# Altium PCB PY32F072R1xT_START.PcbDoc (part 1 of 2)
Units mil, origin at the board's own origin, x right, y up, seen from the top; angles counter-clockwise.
Board outline 1771.65 x 3925.12 mil, 2 copper layers (Top Layer, Bottom Layer), stack 21 mil thick; 156 components, 167 nets, 616 pads, 288 vias.
Unrouted connection lines stored in the file: 5.
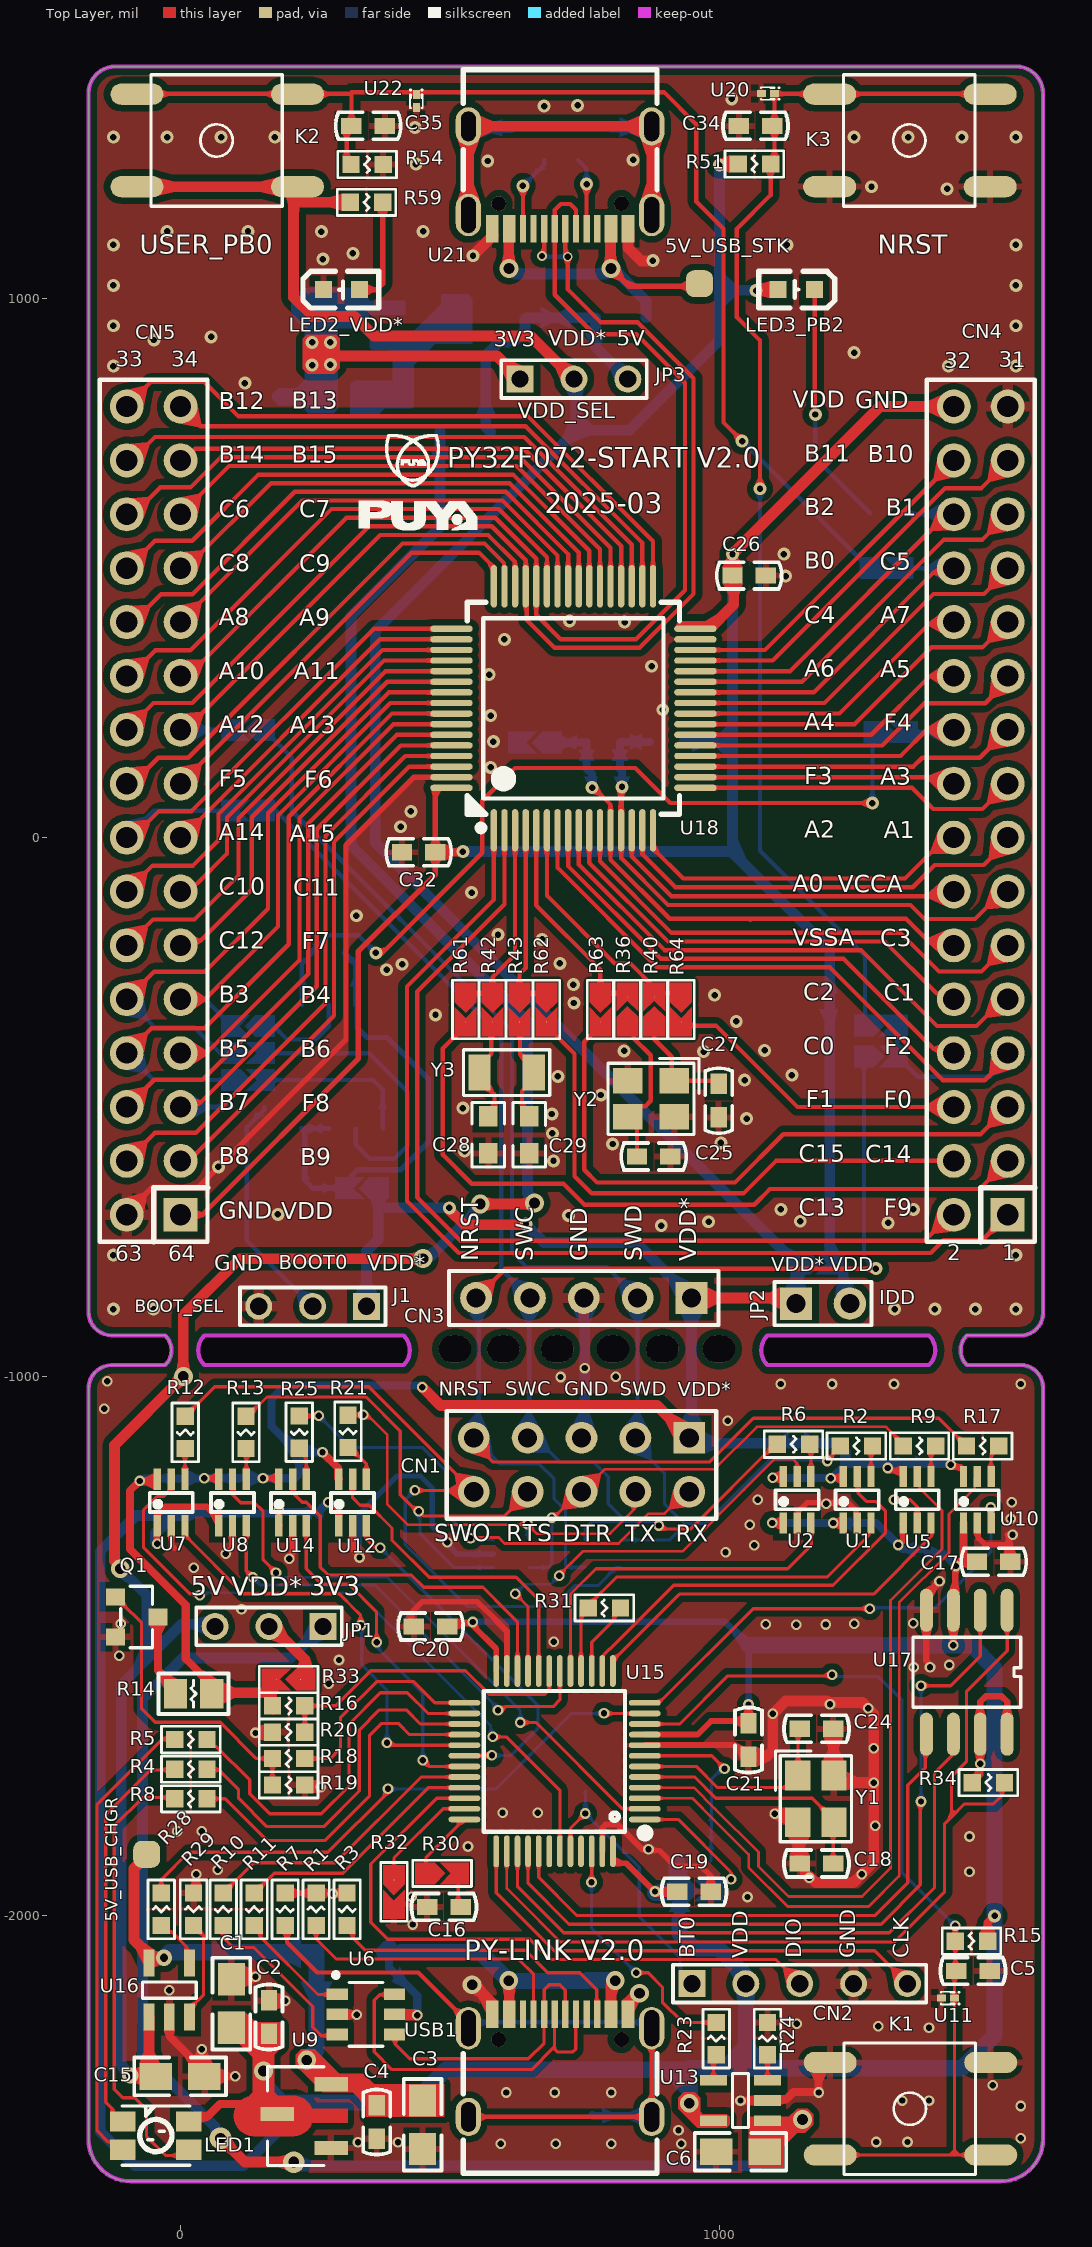
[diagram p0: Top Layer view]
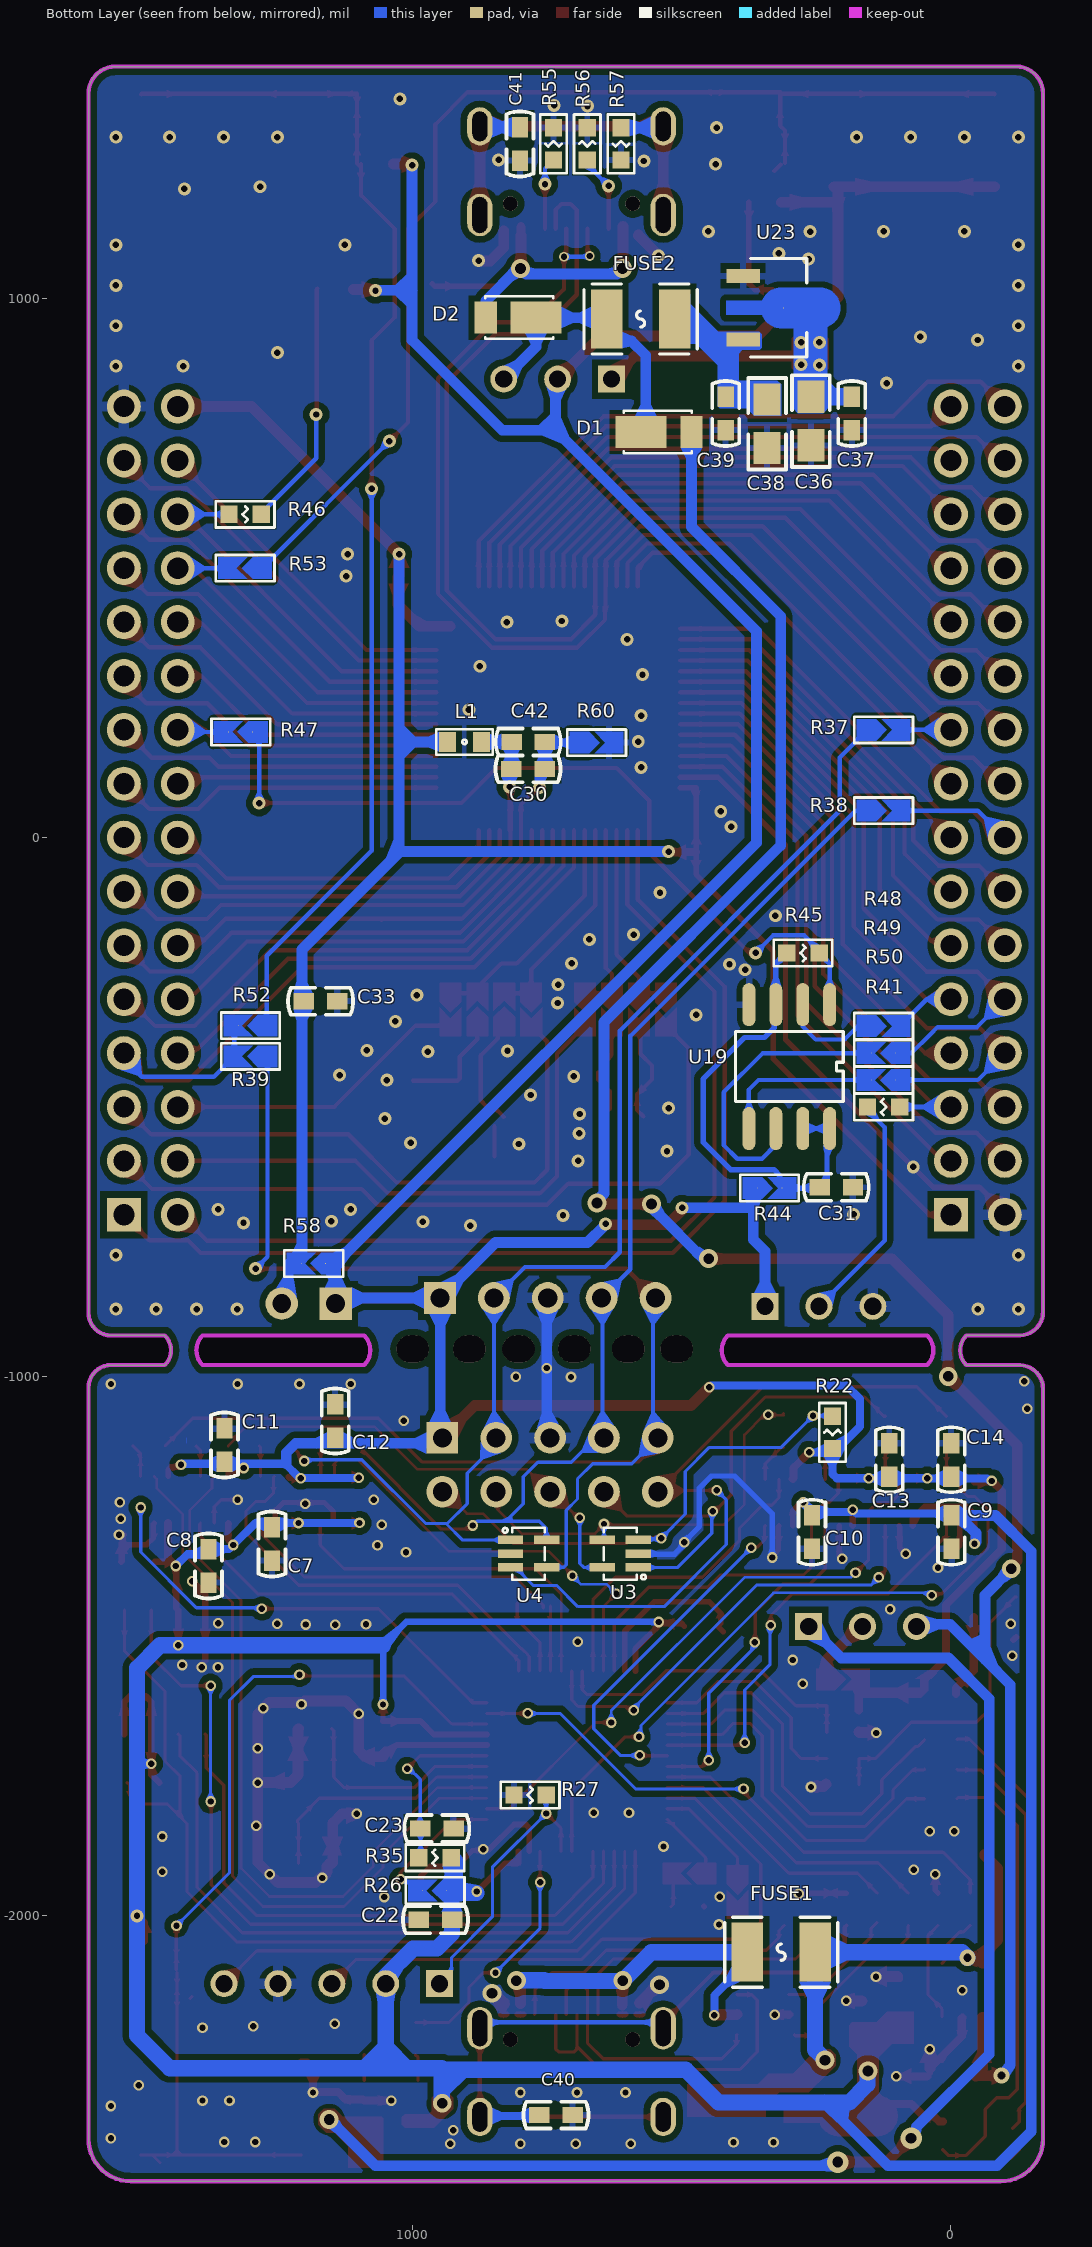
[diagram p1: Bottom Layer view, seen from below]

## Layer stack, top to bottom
Top Solder: solder mask 0.4, Solder Resist, Dk 3.5
Top Layer: signal copper 1.4
Dielectric 2: prepreg 2.8, Composite dielectric, Dk 4.1
Dielectric 1: prepreg 12.6, Composite dielectric, Dk 4.1
Dielectric 3: prepreg 2.8, Composite dielectric, Dk 4.1
Bottom Layer: signal copper 1.4
Bottom Solder: solder mask 0.4, Solder Resist, Dk 3.5

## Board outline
-171,-2415.26 -171,-1024 cw(c-127.25,-1022.75) -128.5,-979 -28.5,-979 ccw(c-56,-951.5) -28.5,-924 -128.5,-924 cw(c-127.25,-880.25) -171,-879 -171,1381.12 cw(c-121,1381.12) -121,1431.12 1550.65,1431.12 cw(c1550.65,1381.12) 1600.65,1381.12 1600.65,-882.35 cw(c1559,-882.35) 1559,-924 1459,-924 ccw(c1486.5,-951.5) 1459,-979 1559,-979 cw(c1559,-1020.65) 1600.65,-1020.65 1600.65,-2415.26 cw(c1521.91,-2415.26) 1521.91,-2494 -92.26,-2494 cw(c-92.26,-2415.26)
cut-out: 1089,-979 cw(c1116.5,-951.5) 1089,-924 1389,-924 cw(c1361.5,-951.5) 1389,-979
cut-out: 44,-979 cw(c71.5,-951.5) 44,-924 414,-924 cw(c386.5,-951.5) 414,-979
cut-out: 44,-979 cw(c71.5,-951.5) 44,-924 414,-924 cw(c386.5,-951.5) 414,-979 394,-979
cut-out: 1089,-979 cw(c1116.5,-951.5) 1089,-924 1389,-924 cw(c1361.5,-951.5) 1389,-979

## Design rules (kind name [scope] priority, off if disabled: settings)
Clearance polygon [InPolygon] p1: gap=12 ignorepadtopadclearanceinfootprint=TRUE
Clearance [All] p2: gap=6 ignorepadtopadclearanceinfootprint=TRUE
HoleToHoleClearance [All] p1: gap=1 allowstackedmicrovias=TRUE
MinimumSolderMaskSliver [All] p1: minsoldermaskwidth=0
PlaneClearance [All] p1: clearance=8
PlaneConnect [All] p1: planeconnectstyle=Direct reliefexpansion=20 reliefentries=4 reliefconductorwidth=10 reliefairgap=10
PolygonConnect [All] p1: thpad.connectstyle=Relief thpad.reliefconductorwidth=20 thpad.reliefentries=4 thpad.polygonreliefangle="90 Angle" thpad.airgapwidth=10 smdpad.connectstyle=Relief smdpad.reliefconductorwidth=12 smdpad.reliefentries=4 smdpad.polygonreliefangle="90 Angle" smdpad.airgapwidth=10 via.connectstyle=Direct via.reliefconductorwidth=10 via.reliefentries=4 via.polygonreliefangle="90 Angle" via.airgapwidth=10
RoutingVias [All] p1: holewidth=28 width=50 viastyle="Through Hole" minholewidth=28 minwidth=50 maxholewidth=28 maxwidth=50
SilkToSilkClearance [All] p1: silktosilkclearance=0
SilkToSolderMaskClearance [IsPad] p1: minsilkscreentomaskgap=0 clearancetoexposedcopper=TRUE
SolderMaskExpansion [All] p1: expansion=4 istentingtop=FALSE
UnRoutedNet [All] p1: checkbadconnections=TRUE
Width [All] p1: maxlimit=100 minlimit=5 preferedwidth=8
23 further rules are at their usual default settings.

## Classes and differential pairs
component class PY32F040R1xT_START: 5V_USB_STK C25 C26 C27 C28 C29 C30 C31 C32 C33 C34 C35 C36 C37 C38 C39 C41 C42 CN3 CN4 CN5 D1 D2 FUSE2 "IDD Test" J1 JP2 JP3 K2 K3 L1 LED2_VDD* LED3_PB2 PF8 R36 R37 R38 R39 R40 R41 R42 R43 R44 R45 R46 R47 R48 R49 R50 R51 R52 R53 R54 R55 R56 R57 R58 R59 R60 R61 R62 R63 R64 ss U18 U19 U20 U21 U22 U23 Y2 Y3
component class PY32F403C1xT_LINK: 5V_USB_CHGR C1 C2 C3 C4 C5 C6 C7 C8 C9 C10 C11 C12 C13 C14 C15 C16 C17 C18 C19 C20 C21 C22 C23 C24 C40 CN1 CN2 FUSE1 JP1 K1 LED1 Q1 R1 R2 R3 R4 R5 R6 R7 R8 R9 R10 R11 R12 R13 R14 R15 R16 R17 R18 R19 R20 R21 R22 R23 R24 R25 R26 R27 R28 R29 R30 R31 R32 R33 R34 R35 ss U1 U2 U3 U4 U5 U6 U7 U8 U9 U10 U11 U12 U13 U14 U15 U16 U17 USB1 Y1

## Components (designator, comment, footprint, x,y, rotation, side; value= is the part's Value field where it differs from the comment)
5V_USB_CHGR "5V_USB_CHGR" TP_SIN -63,-1887 r90 top
5V_USB_STK "5V_USB_STK" TP_SIN 963,1028 r90 top
C1 "10uF" C0805 94,-2164 r270 top
C2 "100nF" C0603 164,-2189 r270 top
C3 "10uF" C0805 449,-2389 r90 top
C4 "100nF" C0603 364,-2384 r90 top
C5 "100nF" C0603 1470.51,-2103.25 r180 top
C6 "10uF" C0805 1039,-2439 r0 top
C7 "100nF" C0603 1260,-1311 r90 bottom value=104
C8 "100nF" C0603 1377.9,-1351.7 r90 bottom value=104
C9 "100nF" C0603 -0.8,-1289.1 r90 bottom value=104
C10 "100nF" C0603 258,-1289.1 r90 bottom value=104
C11 "100nF" C0603 1348.4,-1127.4 r270 bottom value=104
C12 "100nF" C0603 1142.8,-1082.9 r270 bottom value=104
C13 "100nF" C0603 114.5,-1154.8 r270 bottom value=104
C14 "100nF" C0603 -0.5,-1154.8 r270 bottom value=104
C15 "10uF" C0805 -1,-2299 r180 top
C16 "100nF" C0603 488.59,-1984.5 r0 top
C17 "100nF" C0603 1509,-1344 r180 top value=104
C18 "22pF" C0603 1180.12,-1904 r0 top
C19 "100nF" C0603 952.87,-1956.41 r180 top value=104
C20 "100nF" C0603 464,-1464 r0 top value=104
C21 "100nF" C0603 1054.12,-1675 r90 top value=104
C22 "100nF" C0603 956.74,-2008.42 r180 bottom value=104
C23 "100nF" C0603 954.12,-1839 r0 bottom value=104
C24 "22pF" C0603 1180.12,-1654 r180 top
C25 "22pF" C0603 878,-592 r180 top
C26 "100nF" C0603 1055.22,486.24 r0 top
C27 "22pF" C0603 998.67,-488.23 r90 top
C28 "22pF" 0603C 571,-551.5 r270 top
C29 "22pF" 0603C 647,-551.5 r90 top
C30 "100nF" C0603 784.94,127.58 r0 bottom
C31 "100nF/NC" C0603 212.78,-648.93 r0 bottom value=104
C32 "100nF" C0603 441.86,-27.2 r0 top
C33 "4.7uF" C0603 1169.86,-303.63 r0 bottom
C34 "100nF" C0603 1067,1321 r0 top
C35 "100nF" C0603 348,1321 r180 top
C36 "10uF" C0805 260,773 r90 bottom
C37 "100nF" C0603 184,787 r90 bottom
C38 "10uF" C0805 341,768 r90 bottom
C39 "100nF" C0603 418,787 r90 bottom
C40 "4.7nF" C0603 733,-2371 r0 bottom
C41 "4.7nF" C0603 800,1287.5 r90 bottom
C42 "1uF" C0603 784.51,177.65 r180 bottom
CN1 "2X5P" HDR2X5 944,-1114 r180 top
CN2 "CON5" CON5 949,-2127 r0 top
CN3 "Header 5" HDR1X5 948.26,-854.44 r180 top
CN4 "2X16P 2.54mm" HDR-TH_32P-P2.54-V-M-R2-C16-S2.54-3 1485,50 r90 top
CN5 "2X16P 2.54mm" HDR-TH_32P-P2.54-V-M-R2-C16-S2.54-3 -50,50 r90 top
D1 "DFLS130L-7" POWERDI-123_L2.8-W1.8-LS3.7-RD 528.25,753 r180 bottom
D2 "DFLS130L-7" POWERDI-123_L2.8-W1.8-LS3.7-RD 816.75,965 r0 bottom
FUSE1 "BSMD1206-050-6V" SDM1210P005TF 318,-2047 r180 bottom locked
FUSE2 "SMD1210P005TF" SDM1210P005TF 579,984 r180 bottom
J1 "CON3" CON3 345,-869.87 r180 top
JP1 "CON3" CON3 264,-1464 r180 top
JP2 "CON2" CON2 1142,-864.87 r0 top
JP3 "CON3" CON3 630,851 r0 top
K1 "1TS002B-2600-5001_key" Switch 1352.55,-2359 r0 top
K2 "1TS002B-2600-5001_key" Switch 66,1294 r0 top locked
K3 "1TS002B-2600-5001_key" Switch 1351.55,1294 r0 top locked
L1 "BEAD" L0603 902.79,177.53 r180 bottom value=600R@100MHz
LED1 "MHPA3528RGBCT" LED-ARRAY-SMD_4P-L3.5-W2.8-TL -46,-2409 r0 top
LED2_VDD* "RED" 0603_LED 313,1016 r0 top
LED3_PB2 "GREEN" 0603_LED 1128,1018 r180 top
Q1 "2302" SOT23 -81.63,-1446.6 r90 top value=SI2302
R1 "5.1K" R0603 251.49,-1989.01 r270 top
R2 "27R" R0603 1254.21,-1129 r180 top
R3 "5.1K" R0603 309,-1989 r90 top
R4 "680R" R0603 19,-1729 r0 top
R5 "680R" R0603 19,-1674 r0 top
R6 "27R" R0603 1137.39,-1125.9 r180 top
R7 "1M" R0603 194,-1989 r90 top
R8 "680R" R0603 19,-1784 r0 top
R9 "27R" R0603 1371.35,-1129 r180 top
R10 "27R" R0603 79,-1989 r90 top
R11 "27R" R0603 136.5,-1989 r90 top
R12 "27R" R0603 8.66,-1103.92 r90 top
R13 "27R" R0603 121.3,-1103.9 r90 top
R14 "100R" R0805 24,-1589 r0 top
R15 "10K" R0603 1467.76,-2048.15 r0 top
R16 "20K" R0603 200.52,-1611.39 r180 top
R17 "27R" R0603 1488.49,-1129 r180 top
R18 "680R" R0603 200.53,-1709.22 r0 top
R19 "100K" R0603 200.52,-1758.12 r180 top
R20 "10K" R0603 200.53,-1660.31 r0 top
R21 "27R" R0603 310.63,-1101.89 r90 top
R22 "4.7K" R0603 220,-1104 r270 bottom
R23 "5.1K" R0603 994,-2229 r270 top
R24 "16K" R0603 1089,-2229 r270 top
R25 "27R" R0603 220.2,-1103.3 r90 top
R26 "0R" JP2_SMD 957.34,-1954.17 r180 bottom
R27 "10K" R0603 781,-1776.92 r0 bottom
R28 "5.1K" R0603 -36,-1989 r270 top
R29 "16K" R0603 24,-1989 r270 top
R30 "0R" JP2_SMD 485.21,-1922.25 r180 top
R31 "680R" R0603 786.46,-1429.63 r0 top
R32 "0R" JP2_SMD 395.96,-1956.6 r90 top
R33 "0R" JP2_SMD 200.52,-1562.48 r0 top
R34 "100K" R0603 1499,-1754 r180 top
R35 "100K" R0603 957.6,-1893.38 r180 bottom
R36 "0R" JP2_SMD 829,-319 r270 top
R37 "0R" JP2_SMD 125,200 r0 bottom
R38 "0R" JP2_SMD 125,50 r0 bottom
R39 "0R" JP2_SMD 1300,-406 r180 bottom
R40 "0R" JP2_SMD 879,-319 r270 top
R41 "10K" R0603 125,-500 r180 bottom
R42 "0R" JP2_SMD 579,-319 r90 top
R43 "0R" JP2_SMD 629,-319 r90 top
R44 "0R/NC" JP2_SMD 336.72,-650.43 r0 bottom
R45 "100K/NC" R0603 274.57,-214.3 r0 bottom
R46 "680R" R0603 1310,600 r0 bottom
R47 "0R/NC" JP2_SMD 1318,196 r180 bottom
R48 "0R/NC" JP2_SMD 125,-350 r0 bottom
R49 "0R/NC" JP2_SMD 125,-400 r180 bottom
R50 "0R/NC" JP2_SMD 125,-450 r180 bottom
R51 "10K" R0603 1065,1250.24 r0 top
R52 "0R" JP2_SMD 1300,-349 r180 bottom
R53 "0R" JP2_SMD 1310,500 r180 bottom
R54 "5.1K" R0603 346,1249.26 r180 top
R55 "5.1K" R0603 737.5,1287.5 r90 bottom
R56 "5.1K" R0603 675,1287.5 r270 bottom
R57 "1M" R0603 612.5,1287.5 r90 bottom
R58 "0R" JP2_SMD 1182.64,-790.39 r180 bottom
R59 "680R" R0603 345,1179 r180 top
R60 "0R" JP2_SMD 657.63,176.15 r0 bottom
R61 "0R" JP2_SMD 529,-319 r90 top
R62 "0R" JP2_SMD 679,-319 r90 top
R63 "0R" JP2_SMD 779,-319 r90 top
R64 "0R" JP2_SMD 929,-319 r90 top
U1 "74LVC1T45DW" SOT363 1255.64,-1229 r0 top
U2 "74LVC1T45DW" SOT363 1144.21,-1229 r0 top
U3 "ESD_6V1" ESD_SOT323-5L 614,-1329 r90 bottom value=ESDALC6V1W5
U4 "ESD_6V1" ESD_SOT323-5L 784,-1329 r270 bottom value=ESDALC6V1W5
U5 "74LVC1T45DW" SOT363 1367.06,-1229 r0 top locked
U6 "USBLC6-2SC6" SOT23-6 344,-2184 r90 top
U7 "74LVC1T45DW" SOT363 -17.45,-1234 r0 top locked
U8 "74LVC1T45DW" SOT363 96.26,-1234 r0 top
U9 "LM1117-3.3" LM1117-3.3#1 279.38,-2431.9 r0 top
U10 "74LVC1T45DW" SOT363 1478.49,-1229 r0 top
U11 "ESD-TRANSIL" ESD_ST0201 1424,-2154 r180 top value=ESDALC6V1-1U2
U12 "74LVC1T45DW" SOT363 319.12,-1234 r0 top
U13 "MT9700" SOT23-5 1039,-2344 r90 top
U14 "74LVC1T45DW" SOT363 207.69,-1234 r0 top
U15 "PY32F403C1xT" LQFP-48_L7.0-W7.0-P0.50-LS9.0-BL 694,-1714 r90 top locked
U16 "MT9700" SOT23-5 -21,-2139 r0 top
U17 "P25Q64H" SOP-8P 1459,-1549 r180 top value=SST25VF020B
U18 "PY32F072x" LQFP-64_L10.0-W10.0-P0.50-LS12.0-BL 729,240 r0 top locked
U19 "P25Q64H/NC" SOP-8P 300,-425 r0 bottom value=SST25VF020B
U20 "ESD-TRANSIL" ESD_ST0201 1090,1381 r180 top value=ESDALC6V1-1U2
U21 "KH-TYPE-C-16P" USB-C-SMD_KH-TYPE-C-16P 704.2,1225 r180 top locked
U22 "ESD-TRANSIL" ESD_ST0201 437.34,1366.99 r270 top value=ESDALC6V1-1U2
U23 "LM1117-3.3" LM1117-3.3#2 385.84,1042.4 r0 bottom
USB1 "KH-TYPE-C-16P" USB-C-SMD_KH-TYPE-C-16P 704.2,-2279.19 r0 top locked
Y1 "24MHz" CRYSTAL-SMD_4P-L3.2-W2.5-BL 1179.12,-1784 r270 top
Y2 "24MHz" CRYSTAL-SMD_4P-L3.2-W2.5-BL 873,-485 r180 top
Y3 "32.768KHz" CRYSTAL-SMD_L3.2-W1.5-1 605,-436 r180 top value=X503225MSB2GI

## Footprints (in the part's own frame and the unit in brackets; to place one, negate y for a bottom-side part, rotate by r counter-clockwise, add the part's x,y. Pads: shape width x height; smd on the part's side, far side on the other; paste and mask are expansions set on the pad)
0603_LED [mil]
  rect 31.5x31.5 smd: 1(19,1) 2(-48,1)
  silkscreen extent -86,-33 55,35
0603C [mil]
  rect 38x35 smd: 1(-34.5,0) 2(34.5,0)
  silkscreen extent -60,-30 60,30, body extent -31,-16 32,16, height 12
C0603 [mil]
  rect 38x30 smd: 1(-31,0) 2(31,0)
  silkscreen extent -60,-25 60,25
C0805 [mil]
  rect 60x50 smd: 1(-45,0) 2(45,0)
  silkscreen extent -85,-35 85,35
CON2 [mil]
  rect 60x60 hole 35: 1(0,0)
  round 60 hole 35: 2(100,0)
  silkscreen extent -40,-40 140,40
CON3 [mil]
  rect 50x50 hole 32: 1(0,0)
  round 50 hole 32: 2(100,0) 3(200,0)
  silkscreen extent -35,-35 235,35
CON5 [mil]
  rect 50x50 hole 32: 1(0,0)
  round 50 hole 32: 2(100,0) 3(200,0) 4(300,0) 5(400,0)
  silkscreen extent -35,-35 435,35
CRYSTAL-SMD_4P-L3.2-W2.5-BL [mm]
  rect 1.4x1.2 smd: 1(-1.1,-0.85) 2(1.1,-0.85) 3(1.1,0.85) 4(-1.1,0.85)
  silkscreen extent -2.26,-1.91 2.03,1.68
CRYSTAL-SMD_L3.2-W1.5-1 [mm]
  rect 1.05x1.7 smd: 1(-1.275,0) 2(1.275,0)
  silkscreen extent -2.03,-1.08 2.03,1.08
ESD_SOT323-5L [mm]
  rect 0.4x1.2 smd mask+0.05: 1(-0.65,-0.85) 2(0,-0.85) 3(0.65,-0.85) 4(0.65,0.85) 5(-0.65,0.85)
  silkscreen extent -1.23,-1.21 1.23,0.77, body extent -1.15,-1.05 1.15,1.05, height 1.1
ESD_ST0201 [mm]
  rect 0.425x0.33 smd mask+0.05: 1(-0.312,0) 2(0.312,0)
  silkscreen extent -0.55,-0.3 0.33,0.3, body extent -0.34,-0.18 0.34,0.18, height 0.34
HDR1X5 [mm] "Connector; Header; 5 Position"
  rect 1.5x1.5 hole 0.9: 1(0,0)
  round 1.5 hole 0.9: 2(2.54,0) 3(5.08,0) 4(7.62,0) 5(10.16,0)
  silkscreen extent -1.27,-1.27 11.43,1.27
HDR2X5 [mm] "Connector; Header; 4x2 Position"
  rect 1.5x1.5 hole 0.9: 1(0,0)
  round 1.5 hole 0.9: 2(0,2.54) 3(2.54,0) 4(2.54,2.54) 5(5.08,0) 6(5.08,2.54) 7(7.62,0) 8(7.62,2.54) 9(10.16,0) 10(10.16,2.54)
  silkscreen extent -1.27,-1.27 11.43,3.81
HDR-TH_32P-P2.54-V-M-R2-C16-S2.54-3 [mm]
  rect 1.6x1.6 hole 1: 1(-19.05,-1.27)
  round 1.6 hole 1: 2(-19.05,1.27) 3(-16.51,-1.27) 4(-16.51,1.27) 5(-13.97,-1.27) 6(-13.97,1.27) 7(-11.43,-1.27) 8(-11.43,1.27) 9(-8.89,-1.27) 10(-8.89,1.27) 11(-6.35,-1.27) 12(-6.35,1.27) 13(-3.81,-1.27) 14(-3.81,1.27) 15(-1.27,-1.27) 16(-1.27,1.27) 17(1.27,-1.27) 18(1.27,1.27) 19(3.81,-1.27) 20(3.81,1.27) 21(6.35,-1.27) 22(6.35,1.27) 23(8.89,-1.27) 24(8.89,1.27) 25(11.43,-1.27) 26(11.43,1.27) 27(13.97,-1.27) 28(13.97,1.27) 29(16.51,-1.27) 30(16.51,1.27) 31(19.05,-1.27) 32(19.05,1.27)
  silkscreen extent -20.32,-2.54 20.32,2.54
JP2_SMD [mil]
  round 1 smd: 1(21.75,0) 2(-23.03,0.03)
  Top Layer region: -49.77,20.03 -49.77,20.03 3.72,20.03 -16.28,0.03 3.72,-19.98 -49.78,-19.98 -49.78,-19.98
  Top Layer region: -6.25,0 13.75,20 49.75,20 49.75,-20 49.75,-20 13.75,-20
  silkscreen extent -55,-25 54,25
L0603 [mm]
  rect 0.8x0.95 smd mask+0.05: 1(-0.8,0) 2(0.8,0)
  silkscreen extent -1.33,-0.6 1.33,0.6, body extent -0.87,-0.47 0.87,0.47, height 0.95
LED-ARRAY-SMD_4P-L3.5-W2.8-TL [mm]
  rect 1.2x0.95 smd: 1(1.55,0.665) 2(1.55,-0.665) 3(-1.55,-0.665) 4(-1.55,0.665)
  silkscreen extent -1.6,-1.4 1.6,1.4
LM1117-3.3#1 [mm]
  rect 1.575x0.672 smd: 1(0,0) 2(-2.55,1.598) 3(0,3)
  Top Layer region: -3.64,2.459 -1.785,2.459 -1.741,2.458 -1.696,2.455 -1.652,2.449 -1.608,2.442 -1.565,2.433 -1.522,2.421 -1.479,2.408 -1.437,2.393 -1.396,2.375 -1.356,2.356 -1.317,2.335 -1.279,2.312 -1.241,2.288 -1.206,2.261 -1.171,2.233 -1.138,2.204 -1.106,2.173 -1.075,2.14 -1.047,2.106 -1.019,2.071 -0.994,2.034 -0.97,1.996 -0.948,1.958 -0.928,1.918 -0.91,1.839 0.788,1.839 0.788,1.179 -0.91,1.179 -0.928,1.099 -0.948,1.06 -0.97,1.021 -0.994,0.983 -1.019,0.947 -1.047,0.911 -1.075,0.877 -1.106,0.845 -1.138,0.814 -1.171,0.784 -1.206,0.756 -1.241,0.73 -1.279,0.705 -1.317,0.682 -1.356,0.661 -1.396,0.642 -1.437,0.625 -1.479,0.609 -1.522,0.596 -1.565,0.585 -1.608,0.575 -1.652,0.568 -1.696,0.563 -1.741,0.56 -1.785,0.559 -3.64,0.559 -3.684,0.56 -3.728,0.563 -3.773,0.568 -3.817,0.575 -3.86,0.585 -3.903,0.596 -3.946,0.609 -3.988,0.625 -4.029,0.642 -4.069,0.661 -4.108,0.682 -4.146,0.705 -4.183,0.73 -4.219,0.756 -4.254,0.784 -4.287,0.814 -4.319,0.845 -4.349,0.877 -4.378,0.911 -4.405,0.947 -4.431,0.983 -4.455,1.021 -4.477,1.06 -4.497,1.099 -4.515,1.14 -4.531,1.181 -4.546,1.224 -4.558,1.266 -4.568,1.31 -4.577,1.353 -4.583,1.398 -4.587,1.442 -4.589,1.486 -4.589,1.531 -4.587,1.575 -4.583,1.62 -4.577,1.664 -4.568,1.708 -4.558,1.751 -4.546,1.794 -4.531,1.836 -4.515,1.877 -4.497,1.918 -4.477,1.958 -4.455,1.996 -4.431,2.034 -4.405,2.071 -4.378,2.106 -4.349,2.14 -4.319,2.173 -4.287,2.204 -4.254,2.233 -4.219,2.261 -4.183,2.288 -4.146,2.312 -4.108,2.335 -4.069,2.356 -4.029,2.375 -3.988,2.393 -3.946,2.408 -3.903,2.421 -3.86,2.433 -3.817,2.442 -3.773,2.449 -3.728,2.455 -3.684,2.458
  silkscreen extent -3.01,-0.83 -0.35,3.83
LM1117-3.3#2 [mm]
  rect 1.575x0.672 smd: 1(0,0) 3(0,3)
  round 0.025 smd: 2(-1.901,1.509)
  Top Layer region: -3.64,2.459 -1.785,2.459 -1.741,2.458 -1.696,2.455 -1.652,2.449 -1.608,2.442 -1.565,2.433 -1.522,2.421 -1.479,2.408 -1.437,2.393 -1.396,2.375 -1.356,2.356 -1.317,2.335 -1.279,2.312 -1.241,2.288 -1.206,2.261 -1.171,2.233 -1.138,2.204 -1.106,2.173 -1.075,2.14 -1.047,2.106 -1.019,2.071 -0.994,2.034 -0.97,1.996 -0.948,1.958 -0.928,1.918 -0.91,1.839 0.788,1.839 0.788,1.179 -0.91,1.179 -0.928,1.099 -0.948,1.06 -0.97,1.021 -0.994,0.983 -1.019,0.947 -1.047,0.911 -1.075,0.877 -1.106,0.845 -1.138,0.814 -1.171,0.784 -1.206,0.756 -1.241,0.73 -1.279,0.705 -1.317,0.682 -1.356,0.661 -1.396,0.642 -1.437,0.625 -1.479,0.609 -1.522,0.596 -1.565,0.585 -1.608,0.575 -1.652,0.568 -1.696,0.563 -1.741,0.56 -1.785,0.559 -3.64,0.559 -3.684,0.56 -3.728,0.563 -3.773,0.568 -3.817,0.575 -3.86,0.585 -3.903,0.596 -3.946,0.609 -3.988,0.625 -4.029,0.642 -4.069,0.661 -4.108,0.682 -4.146,0.705 -4.183,0.73 -4.219,0.756 -4.254,0.784 -4.287,0.814 -4.319,0.845 -4.349,0.877 -4.378,0.911 -4.405,0.947 -4.431,0.983 -4.455,1.021 -4.477,1.06 -4.497,1.099 -4.515,1.14 -4.531,1.181 -4.546,1.224 -4.558,1.266 -4.568,1.31 -4.577,1.353 -4.583,1.398 -4.587,1.442 -4.589,1.486 -4.589,1.531 -4.587,1.575 -4.583,1.62 -4.577,1.664 -4.568,1.708 -4.558,1.751 -4.546,1.794 -4.531,1.836 -4.515,1.877 -4.497,1.918 -4.477,1.958 -4.455,1.996 -4.431,2.034 -4.405,2.071 -4.378,2.106 -4.349,2.14 -4.319,2.173 -4.287,2.204 -4.254,2.233 -4.219,2.261 -4.183,2.288 -4.146,2.312 -4.108,2.335 -4.069,2.356 -4.029,2.375 -3.988,2.393 -3.946,2.408 -3.903,2.421 -3.86,2.433 -3.817,2.442 -3.773,2.449 -3.728,2.455 -3.684,2.458
  silkscreen extent -3.01,-0.83 -0.35,3.83
LQFP-48_L7.0-W7.0-P0.50-LS9.0-BL [mm]
  oval 0.27x1.5 smd mask+0.05: 1(-2.75,-4.25) 2(-2.25,-4.25) 3(-1.75,-4.25) 4(-1.25,-4.25) 5(-0.75,-4.25) 6(-0.25,-4.25) 7(0.25,-4.25) 8(0.75,-4.25) 9(1.25,-4.25) 10(1.75,-4.25) 11(2.25,-4.25) 12(2.75,-4.25) 25(2.75,4.25) 26(2.25,4.25) 27(1.75,4.25) 28(1.25,4.25) 29(0.75,4.25) 30(0.25,4.25) 31(-0.25,4.25) 32(-0.75,4.25) 33(-1.25,4.25) 34(-1.75,4.25) 35(-2.25,4.25) 36(-2.75,4.25)
  oval 1.5x0.27 smd mask+0.05: 13(4.25,-2.75) 14(4.25,-2.25) 15(4.25,-1.75) 16(4.25,-1.25) 17(4.25,-0.75) 18(4.25,-0.25) 19(4.25,0.25) 20(4.25,0.75) 21(4.25,1.25) 22(4.25,1.75) 23(4.25,2.25) 24(4.25,2.75) 37(-4.25,2.75) 38(-4.25,2.25) 39(-4.25,1.75) 40(-4.25,1.25) 41(-4.25,0.75) 42(-4.25,0.25) 43(-4.25,-0.25) 44(-4.25,-0.75) 45(-4.25,-1.25) 46(-4.25,-1.75) 47(-4.25,-2.25) 48(-4.25,-2.75)
  silkscreen extent -3.59,-4.46 3.3,3.34
LQFP-64_L10.0-W10.0-P0.50-LS12.0-BL [mm]
  oval 0.3x2 smd: 1(-3.75,-5.75) 2(-3.25,-5.75) 3(-2.75,-5.75) 4(-2.25,-5.75) 5(-1.75,-5.75) 6(-1.25,-5.75) 7(-0.75,-5.75) 8(-0.25,-5.75) 9(0.25,-5.75) 10(0.75,-5.75) 11(1.25,-5.75) 12(1.75,-5.75) 13(2.25,-5.75) 14(2.75,-5.75) 15(3.25,-5.75) 16(3.75,-5.75) 33(3.75,5.75) 34(3.25,5.75) 35(2.75,5.75) 36(2.25,5.75) 37(1.75,5.75) 38(1.25,5.75) 39(0.75,5.75) 40(0.25,5.75) 41(-0.25,5.75) 42(-0.75,5.75) 43(-1.25,5.75) 44(-1.75,5.75) 45(-2.25,5.75) 46(-2.75,5.75) 47(-3.25,5.75) 48(-3.75,5.75)
  oval 2x0.3 smd: 17(5.75,-3.75) 18(5.75,-3.25) 19(5.75,-2.75) 20(5.75,-2.25) 21(5.75,-1.75) 22(5.75,-1.25) 23(5.75,-0.75) 24(5.75,-0.25) 25(5.75,0.25) 26(5.75,0.75) 27(5.75,1.25) 28(5.75,1.75) 29(5.75,2.25) 30(5.75,2.75) 31(5.75,3.25) 32(5.75,3.75) 49(-5.75,3.75) 50(-5.75,3.25) 51(-5.75,2.75) 52(-5.75,2.25) 53(-5.75,1.75) 54(-5.75,1.25) 55(-5.75,0.75) 56(-5.75,0.25) 57(-5.75,-0.25) 58(-5.75,-0.75) 59(-5.75,-1.25) 60(-5.75,-1.75) 61(-5.75,-2.25) 62(-5.75,-2.75) 63(-5.75,-3.25) 64(-5.75,-3.75)
  silkscreen extent -5,-5.79 5,5
POWERDI-123_L2.8-W1.8-LS3.7-RD [mm]
  rect 2.4x1.5 smd: 1(-1.187,0)
  rect 1.05x1.5 smd: 2(1.187,0)
  silkscreen extent -2,-1 1.2,1
R0603 [mil]
  rect 32x32 smd: 1(-30,0) 2(30,0)
  silkscreen extent -55,-24 54,25
R0805 [mm]
  rect 1.1x1.4 smd: 1(-0.85,0) 2(0.85,0)
  silkscreen extent -1.65,-0.95 1.65,0.95
SDM1210P005TF [mm]
  rect 1.485x2.781 smd: 1(-1.524,-0.549) 2(1.676,-0.549)
  silkscreen extent -2.59,-2.2 2.74,1.1
SOP-8P [mil]
  oval 24x80 smd: 1(-75,-115) 2(-25,-115) 3(25,-115) 4(75,-115) 5(75,115) 6(25,115) 7(-25,115) 8(-75,115)
  silkscreen extent -100,-65 100,65
SOT23 [mm]
  rect 0.8x0.9 smd: 1(0.95,1) 2(-0.95,1) 3(0,-1)
  silkscreen extent -1.45,-0.75 1.45,0.75
SOT23-5 [mil]
  rect 20x50 smd: 1(-37.5,-50) 2(0,-50) 3(37.5,-50) 4(37.5,50) 5(-37.5,50)
  silkscreen extent -50,-15 50,15
SOT23-6 [mm]
  rect 0.55x1 smd: 1(0.95,1.35) 2(0,1.35) 3(-0.95,1.35) 4(-0.95,-1.35) 5(0,-1.35) 6(0.95,-1.35)
  silkscreen extent -1.5,-0.8 1.96,1.52
SOT363 [mm]
  rect 0.35x1 smd: 1(-0.65,-1.1) 2(0,-1.1) 3(0.65,-1.1) 4(0.65,1.1) 5(0,1.1) 6(-0.65,1.1)
  silkscreen extent -1.02,-0.45 1.02,0.45, body extent -1,-1.1 1,1.16, height 1
Switch [mm]
  oval 2.5x1 smd: 1(-3.734,2.177) 1(3.835,2.177) 2(-3.734,-2.184) 2(3.835,-2.184)
  silkscreen extent -3.08,-3.1 3.12,3.09, body extent -4.48,-3 4.52,3, height 8.95
TP_SIN [mil]
  rrect60% 50x50 smd: 1(0,0)
USB-C-SMD_KH-TYPE-C-16P [mm]
  oval 1.2x2 hole 0.7 slot 1.7 at 90 deg: 1(-4.32,1.765) 2(4.32,1.765)
  oval 1.2x1.8 hole 0.7 slot 1.4 at 90 deg: 3(-4.32,-2.415) 4(4.32,-2.415)
  rect 0.3x1.3 smd: A1(-3.35,2.415) A4(-2.55,2.415) A5(-1.25,2.415) A6(-0.25,2.415) A7(0.25,2.415) A8(1.25,2.415) A9(2.55,2.415) A12(3.35,2.415) B1(3.05,2.415) B4(2.25,2.415) B5(1.75,2.415) B6(0.75,2.415) B7(-0.75,2.415) B8(-1.75,2.415) B9(-2.25,2.415) B12(-3.05,2.415)
  round 0.7 hole 0.7 unplated: ""(-2.89,1.235) ""(2.89,1.235)
  silkscreen extent -4.57,-5.08 4.57,0.57

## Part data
5V_USB_CHGR 5V_USB_STK: library part TP_SIN
C1 C3 C6 C15 C36 C38: library part C0805
C2 C4 C5 C16 C18 C24 C25 C26 C27 C30 C32 C33 C34 C35 C37 C39 C40 C41 C42: library part C0603
C7 C8 C9 C10 C11 C12 C13 C14 C17 C19 C20 C21 C22 C23 C31: library part 贴片高压陶瓷电容, "Capacitor (Semiconductor SIM Model)"
C28 C29: library part Cap, "Capacitor"
CN1: Color=黑色, Current Rating (Max)=-, JLCPCB Part Class="Extended Part", LCSC Part Name="间距:2.54mm 2x5P 直插 方针", Manufacturer=XFCN(兴飞), Manufacturer Part=PZ254V-12-10P, Operating Temperature Range=-40℃~+105℃
CN3: "Header, 5-Pin"
CN4 CN5: Color=黑色, Current Rating (Max)=3A, JLCPCB Part Class="Extended Part", LCSC Part Name="2x16P 间距:2.54mm 方针", Manufacturer="XKB Connection(中国星坤)", Manufacturer Part=X6522WV-2x16H-C60D30-E80, Operating Temperature Range=-40℃~+105℃, Soldering Temperature(Max)=260℃, Voltage Rating (Max)=250V
D1 D2: Average Rectified Current (Io)=1A, Forward Voltage (Vf@If)=310mV@1A, JLCPCB Part Class="Extended Part", LCSC Part Name="电压:30V 电流:1A", Manufacturer=DIODES(美台), Reverse Voltage (Vr)=30V
FUSE1: library part SMD1210P005TF, "https://item.szlcsc.com/947797.html?fromZone=s_s__%25226V%2520500mA%2522"
JP2: library part CON2_DIP
JP3: library part JP3
K1 K2 K3: BOM_JLCPCB Part Class="Extended Part", BOM_Manufacturer=HYP, BOM_Manufacturer Part=1TS002B-2600-5001_KEY
L1: "SMD Chip ferrite bead, 600R@100MHz +/-25%, 350mA, 500mohm DC, 0603, T=0.8mm", Manufacturer=TAI-TECH, Manufacturer_Part_Number=FCM1608KF-601T03
LED1: JLCPCB Part Class=扩展库, LCSC Part Name=RGB三色, Manufacturer=MEIHUA(美华)
LED2_VDD* LED3_PB2: library part PDI-E803_Dup1
Q1: library part "MOSFET N", "MOSFET N"
R1 R2 R3 R4 R5 R6 R7 R8 R9 R10 R11 R12 R13 R15 R16 R17 R18 R19 R20 R21 R22 R23 R24 R25 R26 R27 R28 R29 R30 R31 R32 R33 R34 R35 R36 R37 R38 R39 R40 R41 R42 R43 R44 R45 R46 R47 R48 R49 R50 R51 R52 R53 R54 R55 R56 R57 R58 R59 R60 R61 R62 R63 R64: library part R0603
R14: library part R0805
U3 U4: library part ESDALC6V1W5, "Dual Transil array for ESD protection", Manufacturer=STMICROELECTRONICS
U11 U20 U22: "ESD protection 6V1", Manufacturer=STMICROELECTRONICS, Manufacturer_Part_Number=ESDALC6V1-1U2
U15: "LQFP48", BOM_Manufacturer=PUYA(普冉)
U17 U19: library part SST25VF010, "SST25VF010"
U18: BOM_JLCPCB Part Class="Extended Part", BOM_Manufacturer=ST, BOM_Manufacturer Part=STM32F103VCT6
U21 USB1: BOM_JLCPCB Part Class="Extended Part", BOM_Manufacturer="Shenzhen Kinghelm Elec"
Y1 Y2: library part ABM8AIG-24.000MHZ-82Z-T, "±20ppm , 12.5pF , T_use: -40°C~125°C", Equivalent Series Resistance (ESR)=50Ω, External load capacitor=8pF, Frequency Stability(Full temperature range)=±50ppm, JLCPCB Part Class="Extended Part", LCSC Part Name="24MHz ±20ppm 8pF", Manufacturer=ABRACON, Normal temperature Frequency Tolerance=±20ppm, Operating Temperature=-40℃~+125℃
Y3: library part CRYSTAL_1, "Crystal"

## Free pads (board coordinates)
  oval 60x50 hole 50 slot 60 at 0 deg unplated: 1(509,-949) 1(599,-949) 1(699,-949) 1(802.55,-949) 1(894,-949) 1(999,-949)

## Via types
v1: diameter 24, hole 12, Top Layer to Bottom Layer, tented both sides, 117 vias
v2: diameter 19.68, hole 11.81, Top Layer to Bottom Layer, tented both sides, 109 vias
v3: diameter 19.68, hole 11.81, Top Layer to Bottom Layer, 41 vias
v4: diameter 35, hole 20, Top Layer to Bottom Layer, tented both sides, 15 vias
v5: diameter 17.72, hole 11.81, Top Layer to Bottom Layer, tented both sides, 2 vias
v6: diameter 30, hole 15, Top Layer to Bottom Layer, tented both sides, 2 vias
v7: diameter 40, hole 20, Top Layer to Bottom Layer, tented both sides, 2 vias

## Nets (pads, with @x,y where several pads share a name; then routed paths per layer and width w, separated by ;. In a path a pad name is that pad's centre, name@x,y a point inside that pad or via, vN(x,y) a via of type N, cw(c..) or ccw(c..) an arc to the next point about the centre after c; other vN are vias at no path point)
3.3V_OUT: C36.2 C37.2 JP3.1 U23.2 | length 402.8
  Top Layer w20: 245,894 587,894 JP3.1@630,851
  other v1: 244,877 278,878 244,919 278,919
3.3V_OUT_EN: R23.1 U15.46 | length 463.4
  Top Layer w6: v2(762.49,-1938.91) 762.9,-1938.51 U15.46@762.9,-1881.32 ; v2(845.39,-2106.79) 867.84,-2106.79 894.25,-2133.2 894.25,-2161.62 931.62,-2199 R23.1@994,-2199
  Bottom Layer w6: v2(762.49,-1938.91) 762.49,-2023.89 v2(845.39,-2106.79)
3V3_PYLK: C1.2 C2.2 C7.2 C8.2 C9.2 C10.2 C17.2 C19.2 C20.2 C21.2 C22.2 CN2.2 LED1.1 R15.2 R26.1 R34.2 R35.2 U1.1 U2.1 U5.1 U7.1 U8.1 U9.2 U10.1 U12.1 U13.5 U14.1 U15.9 U15.24 U15.48 U17.3 U17.7 U17.8 | length 8006.2
  Top Layer w10: v2(274.16,-1233.37) 278.42,-1233.37 293.53,-1248.48 U12.1@293.53,-1277.31 ; C20.2@495,-1464 C20.2@499.66,-1459.34 ; C21.2@1054,-1639.88 v2(1054,-1609)
  Top Layer w11: v2@539,-1459 585.73,-1505.73 U15.24@585.73,-1546.68 ; U15.48@802.27,-1881.32 802.27,-1903.39 802.45,-1903.58 827.23,-1903.58 882.65,-1959 v2@884.12,-1959 ; U15.9@861.32,-1664.79 959.39,-1664.79 984.3,-1639.88 C21.2@1054,-1639.88
  Top Layer w12: v3(-43.65,-1310.34) -43.04,-1309.73 U7.1@-43.04,-1277.31 -43.04,-1256.13 -29.04,-1242.12 48.81,-1242.12 70.67,-1263.99 U8.1@70.67,-1277.31 ; U14.1@182.1,-1277.31 182.99,-1276.42 182.12,-1275.54 v2(182.12,-1247.61) ; C20.2@499.66,-1459.34 500.99,-1458.01 539.99,-1458.01 v2(542.28,-1455.72) ; v2(1097.73,-1271.97) 1098.06,-1272.31 U2.1@1118.62,-1272.31 ; v2(1211,-1272.1) 1211.21,-1272.31 U1.1@1230.05,-1272.31 ; v3(1332.01,-1312.98) 1341.47,-1303.52 U5.1@1341.47,-1272.31 1340.58,-1273.2 U5.1@1340.8,-1273.42 ; v2(1434,-1499) U17.3@1434,-1434 1438.01,-1429.99 1438.01,-1352.75 v2(1438.87,-1351.89) ; 1446.76,-1344 C17.2@1478,-1344 ; R34.2@1469,-1754 1484,-1739 v2(1484,-1719) U17.7@1484,-1664 1484,-1604 1494,-1594 1524,-1594 1534,-1604 U17.8@1534,-1664
  Top Layer w15: LED1.1@15.02,-2382.82 22.48,-2382.82 22.48,-2382.34 31.14,-2373.68 50.03,-2373.68 73.3,-2350.41 142.8,-2350.41 ; v2(1438.87,-1351.89) 1446.76,-1344 1452.9,-1337.86 U10.1@1452.9,-1272.31 ; R15.2@1497.76,-2048.15 1497.76,-2014.03 v1(1510.66,-2001.14)
  Top Layer w20: v2@883.87,-1956.41 C19.2@921.87,-1956.41
  Bottom Layer w6: 922.34,-1949.17 927.34,-1954.17
  Bottom Layer w12: v2(542.28,-1455.72) 1010.72,-1455.72 1054,-1499 ; v2(1054,-1609) 1054,-1504 ; v2(1484,-1719) 1513.65,-1719
  Bottom Layer w15: C9.2@2.64,-1254.66 175.07,-1254.66 v2(182.12,-1247.61) 185.92,-1251.4 251.3,-1251.4 C10.2@258,-1258.1 258,-1249.53 v2(274.16,-1233.37) v2@272.56,-1231.78 ; v2(1097.73,-1271.97) 1291,-1271.97 v3(1332.01,-1312.98) 1339.73,-1320.7 C8.2@1377.9,-1320.7 ; C8.2@1387.32,-1330.12 1417.1,-1330.12 v2(1438.87,-1351.89)
  Bottom Layer w20: v3(-43.65,-1310.34) -46.53,-1307.45 -46.53,-1290.88 C9.2@-13.75,-1258.1 ; C9.2@-0.8,-1258.1 -21.6,-1258.1 ; C9.2@-0.8,-1249.8 -13.3,-1249.8 -21.6,-1258.1 ; 234.3,-2347.75 116.88,-2465.16 -85.31,-2465.16 -149,-2401.47 -149,-1324.32 -82.78,-1258.1 -21.6,-1258.1 ; v2(880.39,-1956) 920.65,-1956 925.74,-1956 C22.2@925.74,-2008.42
  Bottom Layer w30: v4(154,-2289) 154.96,-2289.96 154.96,-2314.09 188.61,-2347.75 234.3,-2347.75 431.14,-2347.75 492.2,-2286.68 944.96,-2286.68 ; v2@880.65,-1958.59 920.65,-1958.59 920.65,-1956 R35.2@920.65,-1898.59 ; C22.2@925.74,-2008.42 925.74,-2033.81 953.93,-2062 998.4,-2062 1049,-2112.6 CN2.2@1049,-2127 1049,-2284 ; v4(944,-2349) 944.96,-2348.04 944.96,-2286.68 ; 1054,-1499 v2(1434,-1499) 1467.96,-1499 1510.38,-1541.42 1510.38,-2223.36 1449.74,-2284 1049,-2284 ; 944.96,-2286.68 944.96,-2284 1049,-2284
3V3_USB_PYLK: C6.2 JP1.1 U13.1 | length 2404.2
  Top Layer w20: v7@74.8,-2414 119.03,-2458.23 v7(209.96,-2458.23)
  Bottom Layer w20: v7(74,-2414) 74,-2408.59 64.27,-2398.86 64.27,-2393.02 -70.9,-2257.84 -70.9,-1598.14 4.6,-1522.64 203.6,-1522.64 247.24,-1479 249,-1479 262.24,-1465.76 JP1.1@262.24,-1464 ; v7(209.96,-2458.23) 216.82,-2465.09 1067.91,-2465.09 v4(1154,-2379) v4@1155.78,-2380.78
5V: D1.1 D2.1 FUSE2.1 JP3.3 | length 529.6
  Bottom Layer w20: D1.1@575,753 566.37,761.63 566.37,895.11 593.13,921.86 619.77,921.86 639,941.1 FUSE2.1@639,962.39 641.61,965 D2.1@770,965 770,911 JP3.3@830,851
5V_OUT_EN: R28.1 U15.11 | length 1053.8
  Top Layer w6: R28.1@-36,-1959 -36,-1934 14.65,-1883.35 273.42,-1883.35 384.92,-1771.84 v2(384.92,-1765.58) ; v2(785.76,-1625.47) 785.8,-1625.42 U15.11@861.32,-1625.42
  Bottom Layer w6: v2(384.92,-1765.58) 585.42,-1765.58 725.53,-1625.47 v2(785.76,-1625.47)
5V_USB_CHGR: 5V_USB_CHGR.1 C3.2 C4.2 FUSE1.2 U9.3 U16.5 | length 748.2
  Top Layer w20: 5V_USB_CHGR.1@-63,-1887 -63,-1889.71 -86.6,-1913.31 -86.6,-2045.9 -58.5,-2074 U16.5@-58.5,-2080.91 ; U16.5@-58.5,-2089 U16.5@-58.5,-2080.91 ; v6(-31,-2079) -32.91,-2080.91 U16.5@-58.5,-2080.91
  Bottom Layer w30: v6(-31,-2079) -20.61,-2068.61 FUSE1.2@252.02,-2068.61 252.02,-2249.63 234,-2267.65 v4(234,-2269) v4@233.04,-2268.04
5V_USB_PYLK: C15.2 D1.2 JP1.3 U16.1 | length 4199
  Top Layer w20: v4(-112,-1357) -112,-1352.94 -122.9,-1342.04 -122.9,-1127.76 v4(5,-999.86) 4.89,-999.75 4.89,-886.13 109.57,-781.45 v4(449.71,-781.45) ; v6(-93.61,-2297.18) -92.7,-2298.09 -46.91,-2298.09 C15.2@-46,-2299 ; U16.1@-58.5,-2189.31 -58.5,-2204 -58.81,-2204.31 -58.81,-2284 C15.2@-46,-2284 ; v4(556,-680) v4@649,-680
  Bottom Layer w20: v4(-112,-1357) -62.97,-1406.03 -62.97,-1525 ; v6(-93.61,-2297.18) -96.08,-2296.68 -99.79,-2292.97 -101.19,-2291.57 -110.08,-2278.23 -110.08,-1572.11 -62.97,-1525 ; JP1.3@64,-1464 60.18,-1460.18 1.85,-1460.18 -62.97,-1525 ; v4(449.71,-781.45) 459.58,-781.45 548.5,-692.52 548.5,-691.56 v4@558.24,-681.82 ; D1.2@481.5,753 481.5,576.28 315.99,410.77 315.99,-14.41 643.73,-342.16 643.73,-660.67 657,-673.94 v4(657,-678)
5V_USB_START: 5V_USB_STK.1 D2.2 U21.A4 U21.A9 U21.B4 U21.B9 | length 703.7
  Top Layer w10: v4(798.79,1056.1) 831.63,1023.26 958.26,1023.26 5V_USB_STK.1@963,1028 ; v4@798.79,1057.66 833.19,1023.26
  Top Layer w15: U21.B9@797.98,1117.13 U21.B9@797.98,1135.12
  Top Layer w20: U21.A9@608.8,1134.74 608.8,1057.04 v4(609.45,1056.39) ; v4@797.98,1056.91 U21.B9@797.98,1117.13
  Bottom Layer w20: v4(609.45,1056.39) 619.87,1045.98 788.67,1045.98 v4(798.79,1056.1) 803.34,1056.1 863.5,995.94 D2.2@863.5,965
AD_TVDD: R16.1 R20.2 U15.19 | length 586.3
  Top Layer w6: R20.2@230.52,-1660.3 R16.1@230.52,-1611.39 287.79,-1611.39 352.97,-1546.21 528.66,-1546.21 572.59,-1590.14 675.86,-1590.14 684.16,-1581.83 U15.19@684.16,-1546.68
BOOT0: CN5.5 R41.2 U18.60 | length 1046.2
  Top Layer w8: CN5.5@0,-500 8.48,-491.52 37.04,-491.52 252.71,-275.85 252.71,15.36 408.45,171.1 U18.60@502.63,171.1
  Bottom Layer w10: CN5.5@0,-500 R41.2@95,-500
DIR_RESET: U10.5 U15.3 | length 1394.4
  Top Layer w5: U15.3@861.32,-1782.9 949.66,-1782.9 989.03,-1822.27 1054.22,-1887.45 1054.22,-1911.23 1126.78,-1983.78 1277.12,-1983.78 1333.53,-1927.37 1333.53,-1419.96 1425.97,-1327.53 1425.97,-1255.55 1474.1,-1207.41 1474.1,-1190.08 U10.5@1478.49,-1185.69
DIR_RTCK_DTR: U5.5 U15.4 | length 1362.6
  Top Layer w5: U15.4@861.32,-1763.21 952.69,-1763.21 992.06,-1802.58 1072.43,-1882.95 1072.43,-1909.51 1128.09,-1965.17 1264.95,-1965.17 1317.53,-1912.59 1317.53,-1415.68 1412.97,-1320.24 1412.97,-1248.91 1371.45,-1207.4 1371.45,-1190.08 U5.5@1367.06,-1185.69
DIR_TCK_SWCLK: U2.5 U15.21 | length 808
  Top Layer w5: v2(621.12,-1403.33) 644.79,-1427 U15.21@644.79,-1546.68 ; v3(702.49,-1369.87) 702.49,-1368.43 746.33,-1324.59 931.34,-1324.59 1045.71,-1210.21 1102.38,-1153.54 1136.19,-1153.54 1144.21,-1161.57 U2.5@1144.21,-1185.69
  Bottom Layer w5: v2(621.12,-1403.33) 638.61,-1385.84 686.52,-1385.84 v3(702.49,-1369.87)
DIR_TDI_VCP_TX: U12.5 U15.20 | length 603.7
  Top Layer w6: U12.5@319.12,-1190.69 319.12,-1225.23 332.92,-1239.02 349.97,-1239.02 392.25,-1281.3 392.25,-1304.08 461.11,-1372.94 622.64,-1372.94 664.47,-1414.76 U15.20@664.47,-1546.68
DIR_TDO_SWO: U7.5 U15.43 | length 1242.4
  Top Layer w6: U7.5@-17.45,-1190.69 -17.45,-1209.27 -31.06,-1222.87 -44.03,-1222.87 -68.86,-1247.7 -68.86,-1317.62 16.99,-1403.48 32.93,-1403.48 v3(35.55,-1406.1) ; v2(579,-1669) 604.69,-1669 703.84,-1768.15 U15.43@703.84,-1881.32
  Bottom Layer w5: v3(35.55,-1406.1) 40.05,-1401.59 329.21,-1401.59 575.36,-1647.75 575.36,-1665.36 v2(579,-1669)
DIR_TMS_SWDIO: U1.5 U15.14 | length 784.3
  Top Layer w6: U15.14@782.58,-1546.68 782.58,-1520.01 785.95,-1516.64 785.95,-1515.71 795.51,-1506.15 796.44,-1506.15 915.13,-1387.46 1210.8,-1387.46 1308.4,-1289.87 1308.4,-1250.64 1289.78,-1232.02 1272.79,-1232.02 1257.52,-1216.75 1257.52,-1187.58 U1.5@1255.64,-1185.69
DIR_TRST_RTS: U8.5 U15.2 | length 1100.7
  Top Layer w6: U8.5@96.26,-1190.69 96.85,-1191.28 96.85,-1219.76 111.53,-1234.44 137.14,-1234.44 152.94,-1250.24 152.94,-1340.21 v2(177.06,-1364.33) ; v2(630.52,-1642.32) 659.72,-1642.32 819.98,-1802.58 U15.2@861.32,-1802.58
  Bottom Layer w5: v2(177.06,-1364.33) 185.33,-1372.59 382.59,-1372.59 630.52,-1620.52 v2(630.52,-1642.32)
DIR_VCP_RX: U14.5 U15.22 | length 688.5
  Top Layer w6: U14.5@207.69,-1190.69 209.07,-1192.07 209.07,-1216.86 225.6,-1233.4 233.2,-1233.4 259,-1259.19 259,-1353.94 273.61,-1368.55 428.3,-1368.55 451.05,-1391.29 561.18,-1391.29 605.38,-1435.49 625.1,-1455.21 U15.22@625.1,-1546.68
F_VDD: C31.2 R44.2 R45.2 U19.3 U19.7 U19.8 | length 863
  Bottom Layer w10: U19.7@275,-540 250,-540 U19.8@225,-540 230.06,-545.06 230.06,-635.21 C31.2@243.78,-648.93 245.28,-650.43 306.72,-650.43 317.25,-639.9 317.25,-627.75 328.68,-616.32 409.04,-616.32 460,-565.35 460,-448 383,-371 346,-371 327.68,-352.68 327.68,-312.68 U19.3@325,-310 325,-234.73 R45.2@304.57,-214.3
GND: C1.1 C2.1 C3.1 C4.1 C5.1 C6.1 C7.1 C8.1 C9.1 C10.1 C11.1 C12.1 C13.1 C14.1 C15.1 C16.1 C17.1 C18.1 C19.1 C20.1 C21.1 C22.1 C23.1 C24.1 C25.1 C26.2 C27.1 C28.2 C29.1 C31.1 C32.1 C33.1 C34.1 C35.1 C36.1 C37.1 C38.1 C39.1 C40.1 C41.1 CN1.5 CN2.4 CN3.3 CN4.31 CN5.2 J1.3 K1.1 K3.2 LED2_VDD*.2 Q1.2 R1.1 R3.2 R7.2 R19.1 R20.1 R24.1 R27.2 R29.1 R32.2 R54.1 R55.2 R56.1 R57.1 R60.2 U1.2 U2.2 U3.2 U4.2 U5.2 U6.2 U7.2 U8.2 U9.1 U10.2 U11.2 U12.2 U13.2 U14.2 U15.8 U15.23 U15.47 U16.2 U17.4 U18.31 U18.63 U19.4 U20.2 U21.A1 U21.A12 U21.B1 U21.B12 U22.2 U23.1 USB1.A1 USB1.A12 USB1.B1 USB1.B12 Y1.2 Y1.4 Y2.2 Y2.4 | length 5655.2
  Top Layer w6: v2(1324,-1229) 1354,-1229 1367.06,-1242.06 U5.2@1367.06,-1272.31 ; U11.2@1409.2,-2151.5 U11.2@1411.7,-2154
  Top Layer w10: CN5.2@-100,-700 -100,-696.08 -52.59,-648.67 33.24,-648.67 307,-374.91 307,-13.74 432.79,112.05 U18.63@502.63,112.05 ; U7.2@-17.45,-1277.31 -16.46,-1278.3 -16.46,-1313.92 -11.64,-1318.75 ; R29.1@24,-1959 29,-1954 v2(29,-1924) ; C15.1@39,-2284 39,-2294 C15.1@44,-2299 ; v2(84,-1329.4) 94.89,-1318.51 94.89,-1278.68 U8.2@96.26,-1277.31 ; C1.1@94,-2119 C1.1@99,-2114 ; C2.1@164,-2158 C2.1@165,-2159 ; R7.2@194,-1959 v2@282.95,-1959 ; v2(201.9,-1338.3) 207.59,-1332.61 U14.2@207.59,-1277.41 ; R19.1@230.52,-1758.12 R19.1@232.04,-1756.6 ; v2(282.1,-1959.85) v2@282.95,-1959 ; R3.2@309,-1959 v2@282.95,-1959 ; U12.2@319.12,-1277.31 320.41,-1278.6 320.41,-1321.38 330.83,-1331.8 330.83,-1337.17 v2@329,-1339 ; C20.1@422.36,-1474 432.36,-1464 C20.1@433,-1464 426.95,-1457.95 426.95,-1439.86 448.23,-1418.58 550.98,-1418.58 585.82,-1453.42 ; C16.1@457.59,-1984.5 C16.1@458.59,-1983.5 ; USB1.A1@572.31,-2184.11 USB1.B12@584.12,-2184.11 ; USB1.B1@824.28,-2184.11 USB1.A12@836.09,-2184.11 ; v2@868.47,-1880.44 v2@868.6,-1880.31 ; v2@870.61,-1879.98 888.36,-1879.98 917.57,-1909.2 966.07,-1909.2 983.91,-1927.05 C19.1@983.87,-1956.41 ; U2.2@1143.26,-1273.25 1146.1,-1270.42 1146.1,-1251.05 1163.15,-1234 v2@1199.02,-1234 ; v2(1198.2,-1236.4) 1199.02,-1235.58 v2@1199.02,-1234 ; U1.2@1255.64,-1272.31 1253.75,-1270.42 1253.75,-1248.75 1239,-1234 v2@1199.02,-1234 ; U10.2@1478.49,-1272.31 1480.38,-1274.2 1480.38,-1300.04 1492.61,-1312.28 1539.04,-1312.28 ; CN4.31@1528.58,800 CN4.31@1535,800
  Top Layer w11: 585.82,-1453.42 605.42,-1473.02 U15.23@605.42,-1546.68 ; U15.47@782.58,-1881.32 782.58,-1838.09 788.74,-1831.93 811.08,-1831.93 856.87,-1877.72 v2(868.35,-1877.72) ; U15.8@861.32,-1684.47 1028.94,-1684.47 1050.47,-1706 C21.1@1054.12,-1706
  Top Layer w12: Q1.2@-120.8,-1484.2 Q1.2@-115.99,-1489.01 ; v2(1390.71,-1539.73) 1395.84,-1539.73 1384,-1527.89 1384,-1405.12 1408.39,-1380.73 v2(1408.39,-1380.49) ; v2@1535.2,-1294 1536.67,-1295.47 1536.67,-1307.47 1539.04,-1309.84 1539.04,-1312.28 1539.04,-1343.04 C17.1@1540,-1344
  Top Layer w15: U16.2@-21.52,-2189.52 -20.09,-2190.96 -20.09,-2224.91 C15.1@39,-2284 ; C15.1@44,-2299 v2(101.56,-2299) ; U6.2@299.66,-2183.95 301.24,-2185.53 302.29,-2184.48 v2(327.08,-2184.48) ; v2(1039,-2344) U13.2@1089,-2344 1091.16,-2341.84 1123.66,-2341.84 1137.23,-2328.26 v2@1183.26,-2328.26 ; v2(1184,-2329) 1184,-2284.56 1195.26,-2273.3 K1.1@1205.55,-2273.3
  Top Layer w20: C15.1@39,-2284 v2(39,-2249) ; C1.1@99,-2114 v2(139,-2114) ; v2(138.83,-1661.71) 139.59,-1660.96 170.17,-1660.96 R20.1@170.93,-1660.2 ; C2.1@165,-2159 v2(194,-2159) ; R19.1@232.04,-1756.6 232.04,-1756.88 236.52,-1761.36 258.94,-1761.36 v2(259.7,-1762.13) ; v4(541.08,-2129) 544.03,-2129 USB1.A1@578.17,-2163.15 ; v1@543.38,1080.68 v1(542.61,1079.91) 542.61,1080.42 579.89,1117.7 U21.B1@579.89,1118.54 ; CN1.5@744,-1114 CN1.5@751.47,-1106.53 ; USB1.B1@828.5,-2164.72 v4@848.66,-2144.56 ; U21.B12@829.92,1126.23 829.92,1095.23 854.91,1070.25 v1@874.37,1070.25 ; C21.1@1049.12,-1697 1054.12,-1702 C21.1@1054.12,-1706 1054.41,-1705.72 1087.41,-1705.72 1099.12,-1694 v2(1099.12,-1626.43) 1122.95,-1602.59 1199.41,-1602.59 v2(1205.26,-1608.45) 1206.35,-1608.45 1209.45,-1605.35 1265.47,-1605.35 v2(1276.03,-1615.9) 1286.58,-1626.46 v2(1286.58,-1690.15) 1286.58,-1753.87 1286.58,-1901.54 v2(1264.12,-1924) 1248.85,-1939.27 1178.89,-1939.27 v2@1168.64,-1929.02 ; v2(1102.98,-1811.71) 1130.06,-1811.71 Y1.2@1145.66,-1827.31 1147.39,-1829.04 1147.39,-1902.27 C18.1@1149.12,-1904 1153.12,-1904 1158.12,-1909 1158.12,-1918.5 1159.37,-1919.75 ; 1159.37,-1923.37 v2(1166.83,-1930.82) ; C24.1@1211.12,-1654 1211.85,-1654.73 1211.85,-1739.96 Y1.4@1212.59,-1740.69 1225.74,-1753.84 v2(1286.55,-1753.84)
  Bottom Layer w6: v2@328.26,-1336.17 v2(331.89,-1336.17)
  Bottom Layer w10: v2(331.89,-1336.17) 331.89,-1254.51 401.46,-1184.94 444.72,-1184.94 467,-1207.22 467,-1278.21 494.89,-1306.1 v2(494.89,-1308.11) ; v2@494,-1311 512.72,-1329.72 579.81,-1329.72 U3.2@580.54,-1329
  Bottom Layer w20: CN1.5@744,-1114 750,-1108 750,-856.18 CN3.3@748.26,-854.44 ; CN3.3@750,-854.44 CN3.3@750,-851.06
  other v1: -125,-875 -50,-875 1325,-875 1400,-875 1475,-875 1550,-875 -125,-775 1550,-775 892,-720 1313,-715 980,-713 1150,-712 720,-701 180.66,-699.19 1114,-690 1360,-690 70,-611 692,-600 527,-582 801.75,-568.67 1002.82,-566.73 690,-549 1050.53,-521.67 689,-513 524,-502 779.96,-477.69 1046.69,-450 700,-443 1134.54,-440.88 970.7,-397.26 823,-396 1083.98,-395.09 1031.24,-341.17 473,-329 730,-307 991.21,-292.27 729,-273 382.13,-245.22 411,-235 704.03,-233.55 671,-189 589,-180 326,-145 540,-102 408.13,20.18 427.2,48.65 575.18,130.19 580.33,178.01 575.19,226.42 894.73,237.31 572.46,302.66 874.09,318.03 600.91,367.73 824,400 722,402 1122.71,485.48 1119.7,526.09 119.25,843.62 -125,875 1425,875 1550,875 1250,900 -49.52,923.55 56.68,929.33 -125,950 1550,950 -125,1025 1550,1025 876.47,1070.7 264.05,1073.68 319.5,1084.16 -125,1100 1125,1100 1550,1100 -25,1125 125,1125 261.31,1124.63 450,1125 1422.7,1204.05 1282.18,1207.94 436.72,1249.9 570.01,1255.73 839.66,1257.7 -125,1300 -25,1300 75,1300 175,1300 1250,1300 1350,1300 1450,1300 1550,1300 434.9,1317.85 674.56,1357.55 736.62,1359.07 1022.86,1371.04
  other v2: 594,-2424 696.5,-2424 799,-2424 929,-2424 1291.25,-2421 1349,-2421 1559,-2414 924,-2399 1559,-2354 1339,-2344 1389,-2344 604,-2329 694,-2329 799,-2329 1507.49,-2315.39 1389,-2209 1295.04,-2206.23 1143.39,-2201.64 -21,-2139 1464,-1919 1464,-1854 -6,-1844 39,-1844 1289.12,-1834 -113.7,-1518.66 -111,-1459 1011.35,-1326.43 1544,-1294 1070.94,-1229.05 1114,-1014 1209,-1014 1324,-1014 1559,-1014 -136,-1009
  other v3: 329.23,-2421.27 403.48,-2421.28 430.46,-2017.27 429.2,-1965.8 1052.05,-1966.23 68.93,-1915.82 533.43,-1872.41 662.63,-1810.06 597.47,-1809.5 274.71,-1570.32 1360.33,-1539.47 1426.76,-1535.62 293.86,-1526.38 692.55,-1492.42 1142.59,-1460.94 1197.58,-1460.55 1085.66,-1460.16 1250.24,-1459.37 1359.67,-1458.45 113,-1432 24,-1355 1064.29,-1313.53 1056.19,-1275.1 1540.69,-1264.22 1542.32,-1233.35 1015.59,-1082.46 -141.7,-1059.9 705.13,-1001.17 807.35,-1000.62 750.13,-984.51
  other v4: 851.74,-2144.81
L_USB_CN_DM: U6.4 USB1.A7 USB1.B7 | length 509.2
  Top Layer w6: U6.4@397.15,-2221.4 398.18,-2222.43 398.18,-2239.54 425.04,-2266.4 645.36,-2266.4 674.49,-2237.27 USB1.B7@674.49,-2184.29 ; USB1.B7@674.67,-2184.11 674.7,-2138.3 684,-2129 704,-2129 714,-2139 USB1.A7@714,-2184.07
L_USB_CN_DP: U6.6 USB1.A6 USB1.B6 | length 673
  Top Layer w6: U6.6@397.15,-2146.6 396.26,-2147.49 369.39,-2147.49 359.35,-2157.53 359.35,-2253.6 392.22,-2286.47 651.27,-2286.47 691.55,-2246.19 693.95,-2243.79 ; 694.1,-2244.26 USB1.A6@694.1,-2184.36 ; 694.75,-2249.39 694.75,-2246.19 ; 695.31,-2249.96 699.05,-2253.69 728.06,-2253.69 733.31,-2248.44 USB1.B6@733.31,-2184.52
LED_BLUE: R8.2 U15.28 | length 674.3
  Top Layer w6: R8.2@49,-1784 82.51,-1784 159.7,-1861.19 268.56,-1861.19 350.33,-1779.42 350.33,-1666.59 372.92,-1644 404,-1644 424.79,-1664.79 U15.28@526.68,-1664.79
LED_GREEN: R5.2 U15.26 | length 726.2
  Top Layer w6: R5.2@49,-1674 62,-1687 66.4,-1687 128.27,-1748.87 128.27,-1774.73 165.41,-1811.87 261.27,-1811.87 312.48,-1760.66 312.48,-1645.52 370.75,-1587.25 420.91,-1587.25 459.07,-1625.42 U15.26@526.68,-1625.42
LED_RED: R4.2 U15.27 | length 697.6
  Top Layer w6: R4.2@49,-1729 50.4,-1730.4 70.49,-1730.4 107.6,-1767.52 107.6,-1782.95 160.22,-1835.57 265.52,-1835.57 331.68,-1769.41 331.68,-1656.32 369,-1619 419,-1619 445.1,-1645.1 U15.27@526.68,-1645.1
NetC16_2: C16.2 R30.2 | length 64.1
  Top Layer w6: 515.21,-1922.25 515.21,-1980.12 C16.2@519.59,-1984.5
NetC25_2: C25.2 R36.1 Y2.3 | length 268.9
  Top Layer w8: 829,-349 841,-361 841,-372.63 872.44,-404.07 872.44,-488.56 862.16,-498.84 849.31,-498.84 Y2.3@829.69,-518.47 ; C25.2@847,-592 Y2.3@847,-535.78
NetC27_2: C27.2 R40.1 Y2.1 | length 200.2
  Top Layer w8: 879,-349 879,-374.11 911.6,-406.71 911.6,-446.82 Y2.1@916.31,-451.53 972.53,-451.53 C27.2@998.53,-451.53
